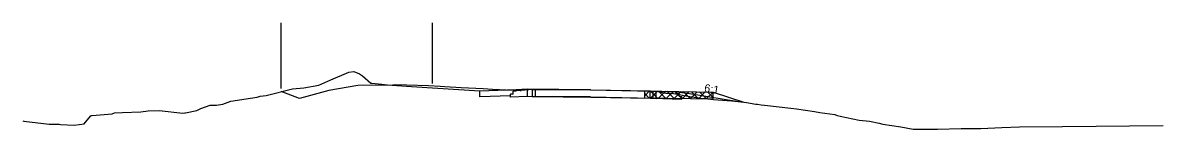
# Model space of a CAD drawing. Extents: x -42 to 262, y 0 to 24.
# Drawn here: x 62.6 to 262.2, y 5 to 23.7 of the extents above; entities that cross this region are included whole.
import ezdxf

# ---------------------------------------------------------------- set-up
doc = ezdxf.new("R2010")
doc.units = 0
for name, color, linetype in [('DT_X_Terrain_Ground_Line', 7, 'Continuous'), ('MT_P_Temp_Road', 7, 'Continuous'), ('TX_P_10', 7, 'Continuous'), ('XS_P_Finished_Grade', 7, 'Continuous'), ('XS_P_Pavt_Surface', 7, 'Continuous'), ('XS_X_Pavt', 7, 'Continuous')]:
    doc.layers.add(name, color=color, linetype=linetype)

msp = doc.modelspace()

# ---------------------------------------------------------------- linework, layer by layer
at = {"layer": 'DT_X_Terrain_Ground_Line'}
for p, q in [((151.79, 11.97), (149.79, 11.79)), ((173.43, 11.68), (175.43, 11.3))]:
    msp.add_line(p, q, dxfattribs=at)
for points in [[(62.59, 6.45), (62.75, 6.43), (67.23, 5.89), (68.59, 5.88), (68.94, 5.87), (69.21, 5.84), (71.59, 5.7), (73.31, 5.92), (74.42, 7.31), (74.47, 7.38), (74.71, 7.4), (78.25, 7.68), (78.62, 7.85), (80.03, 7.93), (83.23, 8.06), (84.54, 8.25), (86.45, 8.26), (90.58, 7.83), (90.94, 7.88), (91.07, 7.89), (93.02, 8.26), (93.74, 8.63), (95.37, 9.21), (96.5, 9.23), (97.62, 9.42), (98.99, 9.93), (102.43, 10.46), (103.6, 10.62), (104.15, 10.82), (105.18, 10.94), (109.8, 12.08), (111.79, 12.25), (114.41, 12.72), (116.51, 13.68), (119.66, 15.02), (120.51, 15.15), (121.49, 14.7), (122.02, 14.35), (123.5, 13.11), (123.69, 13.1), (125.41, 12.91), (126.89, 12.71), (127.82, 12.88), (129.8, 12.8), (133.56, 12.65), (135.64, 12.54), (136.44, 12.51), (139.3, 12.31), (143.15, 12.16), (144.81, 12.03), (149.65, 11.79), (149.79, 11.79)], [(151.79, 11.97), (152.32, 12), (162.01, 11.92), (172.36, 11.72), (173.43, 11.68), (173.43, 11.68)], [(175.43, 11.3), (176.2, 11.31), (176.44, 11.28), (176.81, 11.19), (178.98, 10.79), (181.2, 10.47), (182.02, 10.38), (183.44, 10.23), (185.78, 10.05), (186.69, 9.99), (188.83, 9.74), (189.26, 9.68), (190.86, 9.4), (191.14, 9.38), (191.82, 9.31), (192.36, 9.25), (196.98, 8.7), (197.96, 8.59), (201.14, 8.11), (202.08, 7.96), (204.67, 7.57), (205.09, 7.42), (205.61, 7.28), (208.94, 6.59), (210.76, 6.4), (212.44, 6.06), (213.11, 5.88), (216.22, 5.41), (218.38, 4.99), (222.65, 5.02), (226.82, 5.1), (230.22, 5.14), (233.92, 5.28), (237.03, 5.41), (244.56, 5.47), (262.15, 5.64)]]:
    msp.add_lwpolyline(points, dxfattribs=at)
at = {"layer": 'MT_P_Temp_Road'}
for p, q in [((171.43, 10.53), (171.43, 11.74)), ((171.43, 11.74), (183.43, 11.52)), ((172.28, 11.73), (171.43, 10.88)), ((171.43, 11.26), (172.17, 10.52)), ((171.43, 10.53), (183.43, 10.31)), ((172.38, 11.72), (173.62, 10.49)), ((173.67, 11.7), (172.48, 10.51)), ((173.83, 11.7), (175.06, 10.47)), ((175.06, 11.67), (173.87, 10.49)), ((176.45, 11.65), (175.26, 10.46)), ((175.27, 11.67), (176.5, 10.44)), ((177.83, 11.62), (176.65, 10.44)), ((176.71, 11.64), (177.94, 10.41)), ((179.22, 11.6), (178.04, 10.41)), ((178.15, 11.62), (179.38, 10.38)), ((180.61, 11.57), (179.42, 10.38)), ((179.59, 11.59), (180.82, 10.36)), ((182, 11.54), (180.81, 10.36)), ((181.03, 11.56), (182.26, 10.33)), ((183.39, 11.52), (182.2, 10.33)), ((182.47, 11.53), (183.43, 10.58)), ((183.43, 10.31), (183.43, 11.52)), ((183.43, 11.52), (188.74, 9.75))]:
    msp.add_line(p, q, dxfattribs=at)
at = {"layer": 'TX_P_10'}
for p, q in [((107.83, 12.15), (107.83, 23.7)), ((134.27, 13.02), (134.27, 23.7))]:
    msp.add_line(p, q, dxfattribs=at)
at = {"layer": 'XS_P_Finished_Grade'}
for p, q in [((142.59, 11.67), (130.63, 12.44)), ((111.03, 10.41), (107.83, 11.6)), ((176.93, 11.55), (178.93, 11.35)), ((178.93, 11.35), (188.21, 9.81))]:
    msp.add_line(p, q, dxfattribs=at)
msp.add_lwpolyline([(130.63, 12.44), (126.35, 12.74), (121.24, 12.65), (116.13, 11.81), (111.03, 10.41)], dxfattribs=at)
at = {"layer": 'XS_P_Pavt_Surface'}
for p, q in [((150.93, 12.01), (148.93, 11.93)), ((161.93, 11.92), (150.93, 12.01)), ((150.93, 10.76), (150.93, 12.01)), ((148.93, 11.93), (142.59, 11.67)), ((142.59, 10.67), (142.59, 11.67)), ((147.93, 10.89), (142.59, 10.67)), ((148.43, 11.16), (147.93, 11.14)), ((147.93, 10.64), (147.93, 11.14)), ((150.93, 10.76), (147.93, 10.64)), ((148.93, 11.68), (148.43, 11.66)), ((148.43, 11.16), (148.43, 11.66)), ((148.93, 11.68), (148.93, 11.93)), ((161.93, 10.67), (150.93, 10.76)), ((161.93, 11.92), (172.93, 11.71)), ((161.93, 10.67), (172.93, 10.46)), ((172.93, 10.46), (172.93, 11.71)), ((172.93, 11.71), (176.93, 11.55)), ((172.93, 10.46), (177.93, 10.26)), ((176.93, 11.3), (176.93, 11.55)), ((176.93, 11.3), (177.43, 11.28)), ((177.43, 10.78), (177.43, 11.28)), ((177.43, 10.78), (177.93, 10.76)), ((177.93, 10.26), (177.93, 10.76))]:
    msp.add_line(p, q, dxfattribs=at)
at = {"layer": 'XS_X_Pavt'}
for p, q in [((152.31, 10.72), (152.31, 12)), ((151.79, 10.7), (151.79, 11.97)), ((172.36, 10.45), (172.36, 11.72)), ((173.43, 10.4), (173.43, 11.68))]:
    msp.add_line(p, q, dxfattribs=at)
msp.add_lwpolyline([(151.79, 10.7), (152.32, 10.72), (162.01, 10.65), (172.36, 10.45), (173.43, 10.4)], dxfattribs=at)

# ---------------------------------------------------------------- texts
at = {"layer": 'TX_P_10'}
msp.add_text('6:1', height=1.4, rotation=350.5377, dxfattribs=at).set_placement((181.76, 11.58))

doc.saveas('drawing.dxf')
